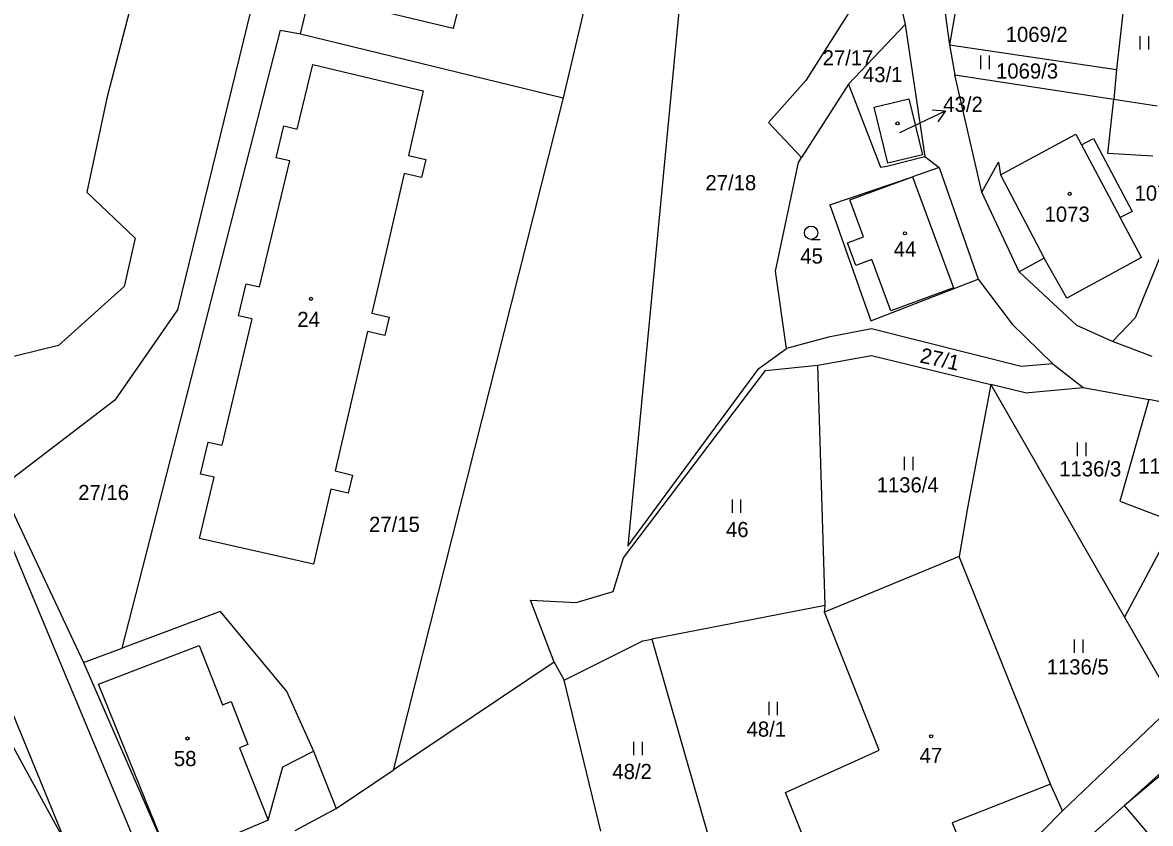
# Model space of a CAD drawing. Extents: x -670359 to -668019, y -978807 to -976674.
# Drawn here: x -670231.3 to -670104.9, y -977801.1 to -977711.4 of the extents above; entities that cross this region are included whole.
import ezdxf

# ---------------------------------------------------------------- set-up
doc = ezdxf.new("R2010")
doc.units = 0
for name, color, linetype in [('Hranice parcel', 7, 'Continuous'), ('Parcelní čísla', 7, 'Continuous'), ('Vnitřní kresba', 7, 'Continuous'), ('Značky budov', 7, 'Continuous'), ('Značky kultur', 7, 'Continuous')]:
    doc.layers.add(name, color=color, linetype=linetype)

msp = doc.modelspace()

# ---------------------------------------------------------------- linework, layer by layer
at = {"layer": 'Hranice parcel'}
for p, q in [((-670108.73, -977716.63), (-670109.04, -977719.94)), ((-670135.87, -977720.84), (-670131.98, -977719.91)), ((-670131.98, -977719.91), (-670130.47, -977726.18)), ((-670134.36, -977727.12), (-670135.87, -977720.84)), ((-670130.47, -977726.18), (-670134.36, -977727.12))]:
    msp.add_line(p, q, dxfattribs=at)
for points in [[(-670163.89, -977539.01), (-670213.94, -977743.56)], [(-670228.39, -977798.54), (-670235.68, -977780.88), (-670248.21, -977752.09), (-670257.66, -977728.06), (-670261.88, -977714.27), (-670262.87, -977707.81), (-670263.3, -977700.83), (-670262.9, -977694.87), (-670261.36, -977686.41), (-670250.36, -977641.2)], [(-670183.39, -977889.81), (-670193.56, -977862.25), (-670201.26, -977845.22), (-670205.62, -977834.5), (-670231.98, -977771.32), (-670242.71, -977745.05), (-670249.53, -977728.04), (-670253.85, -977714.41), (-670254.54, -977710.9), (-670255.07, -977705.75), (-670255.17, -977699.87), (-670254.7, -977694.67), (-670252.82, -977684.15), (-670242.83, -977643.13)], [(-670200.15, -977712.62), (-670185.19, -977651.24)], [(-670156.24, -977658.3), (-670170.72, -977719.8)], [(-670155.4, -977685.45), (-670163.47, -977770.05)], [(-670106.89, -977700.29), (-670108.73, -977716.63)], [(-670217.24, -977701.95), (-670221.85, -977719.84)], [(-670180.99, -977703.63), (-670183.06, -977712.03)], [(-670128.6, -977705.45), (-670127.44, -977713.87)], [(-670183.06, -977712.03), (-670195.6, -977709.06)], [(-670138.55, -977710.02), (-670143.55, -977717.86)], [(-670132.79, -977709.9), (-670132.4, -977711.58)], [(-670138.77, -977718.26), (-670132.4, -977711.58)], [(-670132.4, -977711.58), (-670130.19, -977726.39)], [(-670220.15, -977781.47), (-670202.39, -977712.21)], [(-670202.39, -977712.21), (-670200.15, -977712.62)], [(-670200.15, -977712.62), (-670170.72, -977719.8)], [(-670127.44, -977713.87), (-670108.73, -977716.63)], [(-670127.44, -977713.87), (-670126.84, -977717.22)], [(-670200.51, -977723.32), (-670198.78, -977716.08)], [(-670198.78, -977716.08), (-670186.39, -977719.04)], [(-670143.55, -977717.86), (-670147.72, -977722.56)], [(-670126.84, -977717.22), (-670109.04, -977719.94)], [(-670123.82, -977730.36), (-670126.84, -977717.22)], [(-670186.39, -977719.04), (-670188.06, -977726.25)], [(-670138.77, -977718.26), (-670144.02, -977726.51)], [(-670138.77, -977718.26), (-670135.16, -977727.56)], [(-670221.85, -977719.84), (-670224.09, -977730.38)], [(-670170.72, -977719.8), (-670189.77, -977795.14)], [(-670109.04, -977719.94), (-670104.16, -977720.69)], [(-670202.87, -977726.52), (-670202.02, -977722.96)], [(-670202.02, -977722.96), (-670200.51, -977723.32)], [(-670147.72, -977722.56), (-670144.02, -977726.51)], [(-670121.72, -977728.45), (-670113.29, -977723.87)], [(-670113.29, -977723.87), (-670112.64, -977725.09)], [(-670112.64, -977725.09), (-670111.3, -977724.38)], [(-670111.3, -977724.38), (-670106.95, -977732.55)], [(-670204.74, -977740.99), (-670201.36, -977726.88)], [(-670201.36, -977726.88), (-670202.87, -977726.52)], [(-670188.06, -977726.25), (-670186.12, -977726.7)], [(-670186.12, -977726.7), (-670186.59, -977728.75)], [(-670146.93, -977739.23), (-670144.36, -977727.05)], [(-670144.36, -977727.05), (-670144.02, -977726.51)], [(-670134.44, -977727.48), (-670130.19, -977726.39)], [(-670130.19, -977726.39), (-670128.6, -977727.6)], [(-670099.46, -977726.85), (-670106.63, -977744.47)], [(-670188.54, -977728.29), (-670190.49, -977736.72)], [(-670186.59, -977728.75), (-670188.54, -977728.29)], [(-670135.16, -977727.56), (-670134.44, -977727.48)], [(-670128.6, -977727.6), (-670131.58, -977728.65)], [(-670128.6, -977727.6), (-670124.21, -977740.11)], [(-670140.85, -977731.78), (-670131.58, -977728.65)], [(-670121.72, -977728.45), (-670116.83, -977737.76)], [(-670224.09, -977730.38), (-670218.68, -977735.53)], [(-670119.64, -977739.3), (-670123.82, -977730.36)], [(-670140.85, -977731.78), (-670136.26, -977744.8)], [(-670106.95, -977732.55), (-670108.31, -977733.22)], [(-670105.94, -977737.68), (-670108.31, -977733.22)], [(-670218.68, -977735.53), (-670219.92, -977740.96)], [(-670190.49, -977736.72), (-670192.17, -977743.92)], [(-670114.3, -977742.26), (-670116.83, -977737.76)], [(-670105.94, -977737.68), (-670114.3, -977742.26)], [(-670145.71, -977747.88), (-670146.93, -977739.23)], [(-670113.16, -977745.31), (-670119.64, -977739.3)], [(-670207.11, -977744.23), (-670206.25, -977740.63)], [(-670206.25, -977740.63), (-670204.74, -977740.99)], [(-670136.26, -977744.8), (-670124.21, -977740.11)], [(-670124.21, -977740.11), (-670120.4, -977745.18)], [(-670219.92, -977740.96), (-670227.25, -977747.55)], [(-670213.94, -977743.56), (-670220.97, -977753.67)], [(-670205.59, -977744.58), (-670208.98, -977758.73)], [(-670205.59, -977744.58), (-670207.11, -977744.23)], [(-670192.17, -977743.92), (-670190.22, -977744.37)], [(-670190.22, -977744.37), (-670190.7, -977746.44)], [(-670106.63, -977744.47), (-670109.17, -977747.09)], [(-670192.65, -977745.99), (-670196.27, -977761.61)], [(-670190.7, -977746.44), (-670192.65, -977745.99)], [(-670136.17, -977745.67), (-670140.98, -977746.63)], [(-670119.39, -977749.9), (-670136.17, -977745.67)], [(-670120.4, -977745.18), (-670115.87, -977749.61)], [(-670109.17, -977747.09), (-670113.16, -977745.31)], [(-670140.98, -977746.63), (-670145.71, -977747.88)], [(-670104.74, -977748.8), (-670109.17, -977747.09)], [(-670227.25, -977747.55), (-670234.3, -977749.26)], [(-670148.79, -977750.13), (-670145.71, -977747.88)], [(-670148.05, -977750.34), (-670142.2, -977749.74)], [(-670142.2, -977749.74), (-670136.19, -977748.67)], [(-670141.35, -977776.7), (-670142.2, -977749.74)], [(-670136.19, -977748.67), (-670122.81, -977751.92)], [(-670115.87, -977749.61), (-670119.39, -977749.9)], [(-670115.87, -977749.61), (-670112.45, -977752.27)], [(-670163.96, -977771.35), (-670148.05, -977750.34)], [(-670163.47, -977770.05), (-670148.79, -977750.13)], [(-670122.81, -977751.92), (-670125.43, -977765.74)], [(-670118.94, -977752.86), (-670122.81, -977751.92)], [(-670122.81, -977751.92), (-670107.81, -977777.99)], [(-670118.94, -977752.86), (-670112.45, -977752.27)], [(-670112.45, -977752.27), (-670105.1, -977753.62)], [(-670220.97, -977753.67), (-670233.69, -977763.42)], [(-670105.1, -977753.62), (-670108.36, -977764.99)], [(-670103.42, -977753.93), (-670105.1, -977753.62)], [(-670211.35, -977761.96), (-670210.49, -977758.37)], [(-670210.49, -977758.37), (-670208.98, -977758.73)], [(-670211.48, -977769.17), (-670209.84, -977762.32)], [(-670209.84, -977762.32), (-670211.35, -977761.96)], [(-670196.27, -977761.61), (-670194.32, -977762.07)], [(-670194.32, -977762.07), (-670194.8, -977764.1)], [(-670233.69, -977763.42), (-670224.46, -977783.08)], [(-670196.74, -977763.65), (-670198.7, -977772.06)], [(-670194.8, -977764.1), (-670196.74, -977763.65)], [(-670125.43, -977765.74), (-670126.35, -977771.21)], [(-670108.36, -977764.99), (-670102.16, -977767.34)], [(-670102.16, -977767.34), (-670107.81, -977777.99)], [(-670198.7, -977772.06), (-670211.48, -977769.17)], [(-670126.35, -977771.21), (-670141.44, -977777.42)], [(-670116.13, -977796.71), (-670126.35, -977771.21)], [(-670165.11, -977775.1), (-670163.96, -977771.35)], [(-670171.73, -977783.05), (-670174.4, -977776.07)], [(-670174.4, -977776.07), (-670169.28, -977776.35)], [(-670169.28, -977776.35), (-670165.11, -977775.1)], [(-670241.06, -977776.57), (-670231.37, -977794.32), (-670228.95, -977798.75), (-670226.38, -977803.45)], [(-670209.14, -977777.35), (-670220.15, -977781.47)], [(-670209.14, -977777.35), (-670201.68, -977786.36)], [(-670141.35, -977776.7), (-670160.77, -977780.44)], [(-670141.44, -977777.42), (-670141.35, -977776.7)], [(-670135.31, -977792.9), (-670141.44, -977777.42)], [(-670107.81, -977777.99), (-670102.21, -977787.73)], [(-670170.62, -977785.06), (-670161.79, -977780.64)], [(-670161.79, -977780.64), (-670160.77, -977780.44)], [(-670160.77, -977780.44), (-670154.08, -977803.89)], [(-670224.46, -977783.08), (-670220.15, -977781.47)], [(-670224.46, -977783.08), (-670214.71, -977805.39)], [(-670171.73, -977783.05), (-670189.77, -977795.14)], [(-670171.73, -977783.05), (-670170.62, -977785.06)], [(-670089.7, -977782.74), (-670107.82, -977799.09)], [(-670166.5, -977801.96), (-670170.62, -977785.06)], [(-670201.68, -977786.36), (-670198.69, -977793.02)], [(-670093.41, -977787.03), (-670107.82, -977799.09)], [(-670114.79, -977799.68), (-670102.21, -977787.73)], [(-670202.14, -977794.75), (-670198.69, -977793.02)], [(-670198.69, -977793.02), (-670196.17, -977799.43)], [(-670145.82, -977797.63), (-670135.31, -977792.9)], [(-670203.78, -977800.74), (-670202.14, -977794.75)], [(-670196.17, -977799.43), (-670189.77, -977795.14)], [(-670143.78, -977802.68), (-670145.82, -977797.63)], [(-670114.79, -977799.68), (-670116.13, -977796.71)], [(-670226.38, -977803.45), (-670228.39, -977798.54)], [(-670200.75, -977801.88), (-670196.17, -977799.43)], [(-670123.86, -977808.92), (-670114.79, -977799.68)], [(-670107.82, -977799.09), (-670111.29, -977802.18)], [(-670203.78, -977800.74), (-670214.71, -977805.39)]]:
    msp.add_lwpolyline(points, dxfattribs=at)
at = {"layer": 'Parcelní čísla'}
for p, q in [((-670129.39, -977721.16), (-670127.9, -977721.28)), ((-670133.01, -977723.7), (-670131.51, -977722.99))]:
    msp.add_line(p, q, dxfattribs=at)
msp.add_lwpolyline([(-670131.51, -977722.99), (-670127.9, -977721.28), (-670128.75, -977722.51)], dxfattribs=at)
at = {"layer": 'Vnitřní kresba'}
for points in [[(-670125.04, -977700.04), (-670127.44, -977713.87)], [(-670109.7, -977726.06), (-670109.04, -977719.94)], [(-670112.64, -977725.09), (-670108.31, -977733.22)], [(-670123.82, -977730.36), (-670121.95, -977727.01)], [(-670121.95, -977727.01), (-670121.72, -977728.45)], [(-670104.66, -977726.33), (-670109.7, -977726.06)], [(-670131.58, -977728.65), (-670126.98, -977741.08), (-670134.01, -977743.68), (-670136.14, -977737.92), (-670137.94, -977738.59), (-670138.88, -977736.05), (-670137.08, -977735.39), (-670138.6, -977731.25), (-670131.58, -977728.65)], [(-670116.83, -977737.76), (-670119.64, -977739.3)], [(-670222.8, -977785.49), (-670211.49, -977781.17)], [(-670211.49, -977781.17), (-670208.88, -977787.8)], [(-670214.71, -977805.39), (-670222.8, -977785.49)], [(-670208.88, -977787.8), (-670207.93, -977787.43)], [(-670207.93, -977787.43), (-670206.04, -977792.25)], [(-670206.04, -977792.25), (-670206.98, -977792.62)], [(-670206.98, -977792.62), (-670203.78, -977800.74)], [(-670116.13, -977796.71), (-670127.12, -977801.03)], [(-670100.84, -977807.3), (-670107.82, -977799.09)], [(-670127.12, -977801.03), (-670125, -977806.17)]]:
    msp.add_lwpolyline(points, dxfattribs=at)
at = {"layer": 'Značky budov'}
for centre in [(-670133.26, -977722.67), (-670113.98, -977730.56), (-670132.43, -977735), (-670198.97, -977742.33), (-670212.81, -977791.59), (-670129.49, -977791.34)]:
    msp.add_circle(centre, 0.175, dxfattribs=at)
at = {"layer": 'Značky kultur'}
for p, q in [((-670106.11, -977712.89), (-670106.11, -977714.39)), ((-670105.11, -977714.39), (-670105.11, -977712.89)), ((-670123.96, -977715.08), (-670123.96, -977716.58)), ((-670122.96, -977716.58), (-670122.96, -977715.08)), ((-670142.94, -977735.68), (-670141.94, -977735.68)), ((-670113.14, -977758.44), (-670113.14, -977759.94)), ((-670112.14, -977759.94), (-670112.14, -977758.44)), ((-670132.5, -977760.01), (-670132.5, -977761.51)), ((-670131.5, -977761.51), (-670131.5, -977760.01)), ((-670151.8, -977764.82), (-670151.8, -977766.32)), ((-670150.8, -977766.32), (-670150.8, -977764.82)), ((-670113.45, -977780.48), (-670113.45, -977781.98)), ((-670112.45, -977781.98), (-670112.45, -977780.48)), ((-670147.69, -977787.47), (-670147.69, -977788.97)), ((-670146.69, -977788.97), (-670146.69, -977787.47)), ((-670162.84, -977791.96), (-670162.84, -977793.46)), ((-670161.84, -977793.46), (-670161.84, -977791.96))]:
    msp.add_line(p, q, dxfattribs=at)
for centre, radius in [((-670133.26, -977722.67), 0.175), ((-670113.98, -977730.56), 0.175), ((-670142.94, -977734.93), 0.75), ((-670132.43, -977735), 0.175), ((-670198.97, -977742.33), 0.175), ((-670212.81, -977791.59), 0.175), ((-670129.49, -977791.34), 0.175)]:
    msp.add_circle(centre, radius, dxfattribs=at)

# ---------------------------------------------------------------- texts
at = {"layer": 'Parcelní čísla'}
for s, height, p in [('1069/2', 1.7, (-670121.14, -977713.55)), ('27/17', 1.7, (-670141.65, -977716.18)), ('43/1', 1.7, (-670137.13, -977718.05)), ('1069/3', 1.7, (-670122.22, -977717.65)), ('43/2', 1.7, (-670128.13, -977721.38)), ('43/2', 0.1, (-670133.01, -977723.7)), ('27/18', 1.7, (-670154.78, -977730.16)), ('1074', 1.7, (-670106.7, -977731.33)), ('1073', 1.7, (-670116.78, -977733.69)), ('45', 1.7, (-670144.15, -977738.38)), ('44', 1.7, (-670133.68, -977737.6)), ('24', 1.7, (-670200.51, -977745.48)), ('1136/3', 1.7, (-670115.14, -977762.22)), ('1136/2', 1.7, (-670106.29, -977761.9)), ('1136/4', 1.7, (-670135.6, -977764.02)), ('27/16', 1.7, (-670225.06, -977764.87)), ('27/15', 1.7, (-670192.47, -977768.44)), ('46', 1.7, (-670152.48, -977769.02)), ('1136/5', 1.7, (-670116.55, -977784.41)), ('48/1', 1.7, (-670150.17, -977791.38)), ('47', 1.7, (-670130.78, -977794.33)), ('58', 1.7, (-670214.34, -977794.68)), ('48/2', 1.7, (-670165.21, -977796.13))]:
    msp.add_text(s, height=height, dxfattribs=at).set_placement(p)
msp.add_text('27/1', height=1.7, rotation=347.6508, dxfattribs=at).set_placement((-670130.85, -977749.44))

doc.saveas('drawing.dxf')
